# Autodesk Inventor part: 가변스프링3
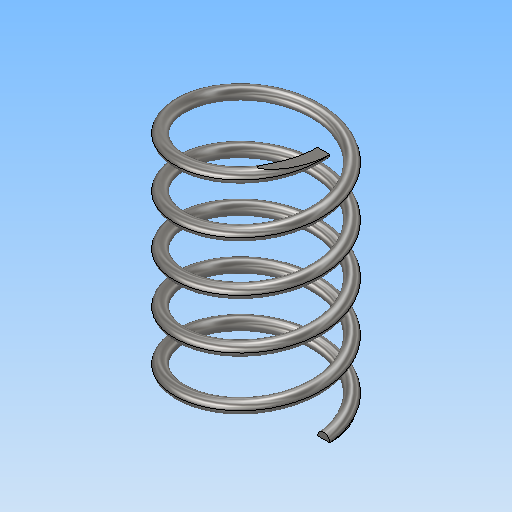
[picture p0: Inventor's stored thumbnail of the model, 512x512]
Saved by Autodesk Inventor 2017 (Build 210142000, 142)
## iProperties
Part Number: 가변스프링3
Material: 강철, 연강
Document SubType Name: Modeling
Designer: MRC
Density: 7.85 g/cm^3
Appearance: 반연마
Mass: 8.43463 g
Surface Area: 21.7444 cm^2
Volume: 1.07448 cm^3
Author: MRC
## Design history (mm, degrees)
sketch "스케치1"
  geometry: L1 (0, 0)-(0, -40.567); L2 (0, 0)-(11, 0); L3 (0, -40.567)-(11.069, -40.567); C1 r 1 at (11, 0)
  constraints: 6 end point, 2 horizontal, 1 centre point, 1 coincident, 1 vertical
  dimensions: "d1" = 22 diameter of L2.end L1; "d2" = 2 diameter of C1; "d4" = 40.56683 distance of L1.start L1.end (derived)
feature "코일1" sketch "스케치1" pitch "d5" = 10; turns "d7" = 5; dims "d6" = 40.56683 (= d4), "d8" = 0, angle "d9" = 90 deg, angle "d10" = 90 deg, "d11" = 0, "d12" = 0
sketch "스케치2"
  geometry: L1 (0, 21.213)-(-40.567, 21.213); L2 (-40.567, 21.213)-(-40.567, -18.04); L3 (-40.567, -18.04)-(0, -18.04); L4 (0, -18.04)-(0, 21.213); 1 further point
  constraints: 8 end point, 2 parallel, 1 horizontal, 1 perpendicular, 1 point on line
  dimensions: "d17" = 40.56683 distance of L2.end L3.end (= d4)
extrude "돌출1" sketch "스케치2" stored distance "d15" = 30; taper "d16" = 0 deg
node "솔리드1"
